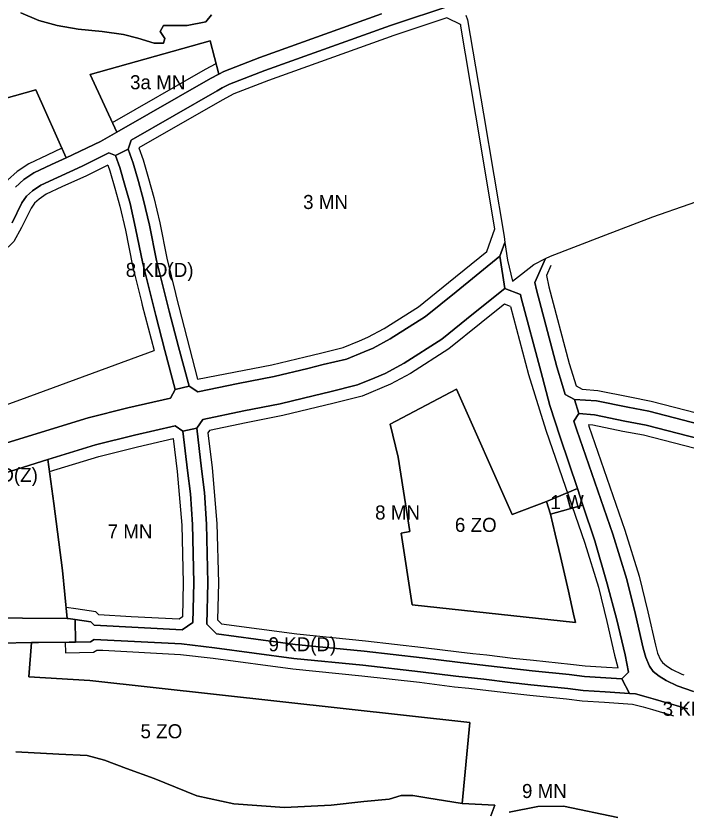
# Model space of a CAD drawing. Extents: x 7418056 to 7420315, y 5537846 to 5539505.
# Drawn here: x 7418849 to 7419326, y 5538474 to 5539041 of the extents above; entities that cross this region are included whole.
import ezdxf

# ---------------------------------------------------------------- set-up
doc = ezdxf.new("R2010")
doc.units = 0
for name, color, linetype in [('linie_rozgraniczajace', 7, 'Continuous'), ('linie_zabudowy_nieprzekraczalne', 7, 'Continuous'), ('oznaczenia_przeznaczen', 7, 'Continuous')]:
    doc.layers.add(name, color=color, linetype=linetype)

msp = doc.modelspace()

# ---------------------------------------------------------------- linework, layer by layer
at = {"layer": 'linie_rozgraniczajace'}
for points in [[(7419160.31, 5539049.03), (7419115.83, 5539034.15), (7419026.26, 5539002.12), (7419001.08, 5538992.37), (7418996.02, 5538989.83), (7418992.47, 5538987.64), (7418931.07, 5538952.54), (7418928.94, 5538946.14), (7418919.94, 5538941.63), (7418915.16, 5538943.43), (7418913.94, 5538942.73), (7418896.26, 5538934.01), (7418878.7, 5538926.05), (7418866.85, 5538920.51), (7418860.9, 5538916.51), (7418856.55, 5538912.53), (7418853.39, 5538907.77), (7418846.35, 5538893.73)], [(7419169.45, 5539041.55), (7419170.63, 5539038.31), (7419182.09, 5538971.36), (7419196.68, 5538883.86), (7419197.31, 5538879.71), (7419193.8, 5538869.94), (7419162.51, 5538844.52), (7419140.66, 5538826.97), (7419115.55, 5538810.89), (7419103.46, 5538804.38), (7419097.12, 5538801.74), (7419084.62, 5538796.58), (7419067.95, 5538792.6), (7419057.02, 5538789.95), (7419033.05, 5538784.14), (7419007.36, 5538779.18), (7418978.69, 5538773.11), (7418972.52, 5538777.28), (7418964.83, 5538805.21), (7418958.22, 5538830.78), (7418949.28, 5538866.87), (7418944.15, 5538892.03), (7418940.07, 5538909.81), (7418936.36, 5538923.15), (7418932.65, 5538936.07), (7418928.94, 5538946.14), (7418931.07, 5538952.54), (7418992.47, 5538987.64), (7418996.02, 5538989.83), (7419001.08, 5538992.37), (7419026.26, 5539002.12), (7419115.83, 5539034.15), (7419160.31, 5539049.03)], [(7418848.89, 5538919.08), (7418854.7, 5538924.41), (7418861.91, 5538929.24), (7418874.51, 5538935.14), (7418884.95, 5538939.87), (7418909.25, 5538951.55), (7418921.06, 5538958.34), (7418987.73, 5538996.53), (7418993.51, 5538999.62), (7418997.17, 5539001.58), (7419022.76, 5539011.49), (7419109.39, 5539042.47)], [(7418852.68, 5539043.27), (7418865.34, 5539037.9), (7418878.57, 5539034.27), (7418893.38, 5539031.69), (7418910.45, 5539029.88), (7418925.8, 5539027.87), (7418935.87, 5539025.18), (7418947.51, 5539021.65), (7418954.26, 5539021.67), (7418955.12, 5539024.96), (7418951.91, 5539030.07), (7418954.09, 5539034.36), (7418970.99, 5539034.34), (7418984.37, 5539036.89), (7418988.28, 5539041.83)], [(7418988.28, 5539041.83), (7418984.37, 5539036.89), (7418970.99, 5539034.34), (7418954.09, 5539034.36), (7418951.91, 5539030.07), (7418955.12, 5539024.96), (7418954.26, 5539021.67), (7418947.51, 5539021.65), (7418935.87, 5539025.18), (7418925.8, 5539027.87), (7418910.45, 5539029.88), (7418893.38, 5539031.69), (7418878.57, 5539034.27), (7418865.34, 5539037.9), (7418852.68, 5539043.27)], [(7419109.39, 5539042.47), (7419022.76, 5539011.49), (7418997.17, 5539001.58)], [(7418997.17, 5539001.58), (7418993.51, 5538999.62), (7418987.39, 5539023.42), (7418902.04, 5538999.34), (7418921.06, 5538958.34), (7418909.25, 5538951.55), (7418884.95, 5538939.87), (7418863.26, 5538988.38), (7418809.94, 5538973.34)], [(7418809.94, 5538973.34), (7418863.26, 5538988.38), (7418884.95, 5538939.87), (7418874.51, 5538935.14), (7418861.91, 5538929.24), (7418854.7, 5538924.41), (7418848.89, 5538919.08)], [(7418846.35, 5538893.73), (7418853.39, 5538907.77), (7418856.55, 5538912.53), (7418860.9, 5538916.51), (7418866.85, 5538920.51), (7418878.7, 5538926.05), (7418896.26, 5538934.01), (7418913.94, 5538942.73), (7418915.16, 5538943.43), (7418919.94, 5538941.63), (7418923.14, 5538932.95), (7418926.74, 5538920.43), (7418930.38, 5538907.35), (7418934.37, 5538889.91), (7418939.52, 5538864.68), (7418948.74, 5538827.5), (7418955.15, 5538802.69), (7418962.6, 5538774.99), (7418959.07, 5538768.78), (7418928.88, 5538761.73), (7418900.44, 5538754.64), (7418830.07, 5538733.01)], [(7419445.05, 5538721.75), (7419299.76, 5538759.34), (7419284.77, 5538762.18), (7419262.47, 5538766.8), (7419246.91, 5538767.82), (7419240.3, 5538771.3), (7419238.22, 5538777.64), (7419234.4, 5538791.06), (7419219.93, 5538845.79), (7419218.69, 5538851.22), (7419226.21, 5538868.16), (7419229.78, 5538869.96), (7419266.22, 5538883.99), (7419302.67, 5538898.01), (7419354.38, 5538915.86)], [(7419193.8, 5538869.94), (7419197.31, 5538879.71), (7419199.26, 5538867.11), (7419202.74, 5538852.14), (7419209.04, 5538857.05), (7419217.86, 5538863.95), (7419226.21, 5538868.16), (7419218.69, 5538851.22), (7419219.93, 5538845.79), (7419234.4, 5538791.06), (7419238.22, 5538777.64), (7419240.3, 5538771.3), (7419246.91, 5538767.82), (7419249.9, 5538757.72), (7419246.5, 5538752.37), (7419248.59, 5538745.99), (7419274.18, 5538671.86), (7419284.18, 5538639.55), (7419290.38, 5538614.44), (7419295.8, 5538590.55), (7419297.6, 5538583.9), (7419300.28, 5538577.86), (7419302.97, 5538574.06), (7419307.22, 5538570.67), (7419312.08, 5538567.46), (7419319.89, 5538563.81), (7419331.61, 5538559.58)], [(7418830.07, 5538733.01), (7418900.44, 5538754.64), (7418928.88, 5538761.73), (7418959.07, 5538768.78), (7418962.6, 5538774.99), (7418972.52, 5538777.28), (7418978.69, 5538773.11), (7419007.36, 5538779.18), (7419033.05, 5538784.14), (7419057.02, 5538789.95), (7419067.95, 5538792.6), (7419084.62, 5538796.58), (7419097.12, 5538801.74), (7419103.46, 5538804.38), (7419115.55, 5538810.89), (7419140.66, 5538826.97), (7419162.51, 5538844.52), (7419193.8, 5538869.94), (7419197.25, 5538846.73), (7419175.03, 5538828.93), (7419152.35, 5538810.7), (7419125.7, 5538793.64), (7419112.07, 5538786.3), (7419104.79, 5538783.26), (7419092.25, 5538778.09), (7419072.64, 5538773.16), (7419061.83, 5538770.53), (7419037.31, 5538764.59), (7419011.32, 5538759.57), (7418982.12, 5538753.4), (7418977.82, 5538747.4), (7418968.01, 5538745.28), (7418962.54, 5538749.08), (7418933.57, 5538742.29), (7418905.8, 5538735.36), (7418871.76, 5538724.9), (7418836.1, 5538713.94)], [(7419327.41, 5538547.33), (7419319.28, 5538549.7), (7419312.66, 5538551.61), (7419304.62, 5538553.96), (7419297.92, 5538555.91), (7419290.4, 5538558.1), (7419285.99, 5538558.34), (7419280.63, 5538568.76), (7419285.24, 5538573.49), (7419282.94, 5538585.76), (7419277.11, 5538610.78), (7419270.23, 5538636.52), (7419261.4, 5538667.14), (7419252.88, 5538692.56), (7419248.94, 5538704.31), (7419236.65, 5538740.96), (7419229.28, 5538763.46), (7419222.83, 5538787.88), (7419209, 5538840.19), (7419208.37, 5538842.57), (7419197.25, 5538846.73), (7419193.8, 5538869.94)], [(7419442.55, 5538712.07), (7419297.9, 5538749.52), (7419282.83, 5538752.37), (7419261.07, 5538756.88), (7419249.9, 5538757.72), (7419246.91, 5538767.82), (7419262.47, 5538766.8), (7419284.77, 5538762.18), (7419299.76, 5538759.34), (7419445.05, 5538721.75)], [(7419331.61, 5538559.58), (7419319.89, 5538563.81), (7419312.08, 5538567.46), (7419307.22, 5538570.67), (7419302.97, 5538574.06), (7419300.28, 5538577.86), (7419297.6, 5538583.9), (7419295.8, 5538590.55), (7419290.38, 5538614.44), (7419284.18, 5538639.55), (7419274.18, 5538671.86), (7419248.59, 5538745.99), (7419246.5, 5538752.37), (7419249.9, 5538757.72), (7419261.07, 5538756.88), (7419282.83, 5538752.37), (7419297.9, 5538749.52), (7419442.55, 5538712.07)], [(7418836.1, 5538713.94), (7418871.76, 5538724.9), (7418876.01, 5538693.69), (7418882.21, 5538645.85), (7418885.71, 5538611.77), (7418853.86, 5538611.94), (7418837.03, 5538612.11)], [(7418837.03, 5538612.11), (7418853.86, 5538611.94), (7418885.71, 5538611.77), (7418886.34, 5538611.65), (7418891.32, 5538611.05), (7418891.64, 5538594.92), (7418887.02, 5538594.78), (7418865.29, 5538594.71), (7418860.23, 5538594.58), (7418838.16, 5538594.04)], [(7418838.16, 5538594.04), (7418860.23, 5538594.58), (7418858.38, 5538570.15), (7418901.82, 5538567.44), (7419172.23, 5538537.66), (7419166.81, 5538479.9), (7419141.82, 5538484.04), (7419131.75, 5538485.55), (7419123.56, 5538485.53), (7419114.83, 5538482.98), (7419096.93, 5538481.3), (7419073.69, 5538478.78), (7419040.33, 5538477.11), (7419004.29, 5538479.75), (7418977.88, 5538485.29), (7418947.59, 5538497.69), (7418927.76, 5538504.76), (7418912.06, 5538510.74), (7418899.95, 5538514.03), (7418879.72, 5538515.1), (7418849.07, 5538516.69)], [(7419187.23, 5538471.09), (7419190.15, 5538478.7), (7419166.81, 5538479.9), (7419172.23, 5538537.66), (7418901.82, 5538567.44), (7418858.38, 5538570.15), (7418860.23, 5538594.58), (7418865.29, 5538594.71), (7418887.02, 5538594.78), (7418891.64, 5538594.92), (7418902.09, 5538595.12), (7418904.86, 5538596.86), (7418966.99, 5538593.54), (7418990.58, 5538590.89), (7419047.02, 5538583.32), (7419096.11, 5538578.4), (7419137.33, 5538573.76), (7419162.43, 5538570.57), (7419182.35, 5538568.37), (7419201.04, 5538566.12), (7419215.74, 5538564.54), (7419242.02, 5538561.82), (7419252.98, 5538560.44), (7419268.68, 5538559.53), (7419285.99, 5538558.34), (7419290.4, 5538558.1), (7419297.92, 5538555.91), (7419304.62, 5538553.96), (7419312.66, 5538551.61), (7419319.28, 5538549.7), (7419327.41, 5538547.33)], [(7418849.07, 5538516.69), (7418879.72, 5538515.1), (7418899.95, 5538514.03), (7418912.06, 5538510.74), (7418927.76, 5538504.76), (7418947.59, 5538497.69), (7418977.88, 5538485.29), (7419004.29, 5538479.75), (7419040.33, 5538477.11), (7419073.69, 5538478.78), (7419096.93, 5538481.3), (7419114.83, 5538482.98), (7419123.56, 5538485.53), (7419131.75, 5538485.55), (7419141.82, 5538484.04), (7419166.81, 5538479.9), (7419190.15, 5538478.7), (7419187.23, 5538471.09)], [(7419277.73, 5538469.82), (7419238.97, 5538477.94), (7419220.85, 5538477.69), (7419200.36, 5538473.67)], [(7419200.36, 5538473.67), (7419220.85, 5538477.69), (7419238.97, 5538477.94), (7419277.73, 5538469.82)]]:
    msp.add_lwpolyline(points, dxfattribs=at)
for points in [[(7418902.04, 5538999.34), (7418987.39, 5539023.42), (7418993.51, 5538999.62), (7418987.73, 5538996.53), (7418921.06, 5538958.34)], [(7418919.94, 5538941.63), (7418928.94, 5538946.14), (7418932.65, 5538936.07), (7418936.36, 5538923.15), (7418940.07, 5538909.81), (7418944.15, 5538892.03), (7418949.28, 5538866.87), (7418958.22, 5538830.78), (7418964.83, 5538805.21), (7418972.52, 5538777.28), (7418962.6, 5538774.99), (7418955.15, 5538802.69), (7418948.74, 5538827.5), (7418939.52, 5538864.68), (7418934.37, 5538889.91), (7418930.38, 5538907.35), (7418926.74, 5538920.43), (7418923.14, 5538932.95)], [(7418977.82, 5538747.4), (7418982.12, 5538753.4), (7419011.32, 5538759.57), (7419037.31, 5538764.59), (7419061.83, 5538770.53), (7419072.64, 5538773.16), (7419092.25, 5538778.09), (7419104.79, 5538783.26), (7419112.07, 5538786.3), (7419125.7, 5538793.64), (7419152.35, 5538810.7), (7419175.03, 5538828.93), (7419197.25, 5538846.73), (7419208.37, 5538842.57), (7419209, 5538840.19), (7419222.83, 5538787.88), (7419229.28, 5538763.46), (7419236.65, 5538740.96), (7419248.94, 5538704.31), (7419226.86, 5538694.97), (7419202.55, 5538685.76), (7419162.85, 5538775.08), (7419115.51, 5538750.08), (7419121.22, 5538726.71), (7419129.55, 5538673.65), (7419123.39, 5538672.41), (7419131.25, 5538621.36), (7419247.63, 5538608.96), (7419246.27, 5538614.84), (7419242.51, 5538631.17), (7419236.8, 5538655.87), (7419233.15, 5538671.75), (7419229.7, 5538685.93), (7419252.88, 5538692.56), (7419261.4, 5538667.14), (7419270.23, 5538636.52), (7419277.11, 5538610.78), (7419282.94, 5538585.76), (7419285.24, 5538573.49), (7419280.63, 5538568.76), (7419269.29, 5538569.51), (7419253.9, 5538570.41), (7419243.15, 5538571.75), (7419216.79, 5538574.48), (7419202.18, 5538576.05), (7419183.5, 5538578.31), (7419163.61, 5538580.5), (7419138.52, 5538583.69), (7419097.17, 5538588.34), (7419048.02, 5538593.27), (7418991.91, 5538600.79), (7418984.98, 5538607.62), (7418985.77, 5538637.14), (7418984.74, 5538679.01), (7418983.39, 5538701.43), (7418981.32, 5538718.3)], [(7419115.51, 5538750.08), (7419162.85, 5538775.08), (7419202.55, 5538685.76), (7419226.86, 5538694.97), (7419229.7, 5538685.93), (7419233.15, 5538671.75), (7419236.8, 5538655.87), (7419242.51, 5538631.17), (7419246.27, 5538614.84), (7419247.63, 5538608.96), (7419131.25, 5538621.36), (7419123.39, 5538672.41), (7419129.55, 5538673.65), (7419121.22, 5538726.71)], [(7418871.76, 5538724.9), (7418905.8, 5538735.36), (7418933.57, 5538742.29), (7418962.54, 5538749.08), (7418968.01, 5538745.28), (7418971.4, 5538717.1), (7418973.42, 5538700.53), (7418974.75, 5538678.59), (7418975.77, 5538637.14), (7418975.02, 5538608.95), (7418967.53, 5538603.53), (7418904.75, 5538606.91), (7418902.39, 5538609.43), (7418891.32, 5538611.05), (7418886.34, 5538611.65), (7418885.71, 5538611.77), (7418882.21, 5538645.85), (7418876.01, 5538693.69)], [(7418891.64, 5538594.92), (7418891.32, 5538611.05), (7418902.39, 5538609.43), (7418904.75, 5538606.91), (7418967.53, 5538603.53), (7418975.02, 5538608.95), (7418975.77, 5538637.14), (7418974.75, 5538678.59), (7418973.42, 5538700.53), (7418971.4, 5538717.1), (7418968.01, 5538745.28), (7418977.82, 5538747.4), (7418981.32, 5538718.3), (7418983.39, 5538701.43), (7418984.74, 5538679.01), (7418985.77, 5538637.14), (7418984.98, 5538607.62), (7418991.91, 5538600.79), (7419048.02, 5538593.27), (7419097.17, 5538588.34), (7419138.52, 5538583.69), (7419163.61, 5538580.5), (7419183.5, 5538578.31), (7419202.18, 5538576.05), (7419216.79, 5538574.48), (7419243.15, 5538571.75), (7419253.9, 5538570.41), (7419269.29, 5538569.51), (7419280.63, 5538568.76), (7419285.99, 5538558.34), (7419268.68, 5538559.53), (7419252.98, 5538560.44), (7419242.02, 5538561.82), (7419215.74, 5538564.54), (7419201.04, 5538566.12), (7419182.35, 5538568.37), (7419162.43, 5538570.57), (7419137.33, 5538573.76), (7419096.11, 5538578.4), (7419047.02, 5538583.32), (7418990.58, 5538590.89), (7418966.99, 5538593.54), (7418904.86, 5538596.86), (7418902.09, 5538595.12)], [(7419226.86, 5538694.97), (7419248.94, 5538704.31), (7419252.88, 5538692.56), (7419229.7, 5538685.93)]]:
    msp.add_lwpolyline(points, close=True, dxfattribs=at)
at = {"layer": 'linie_zabudowy_nieprzekraczalne'}
for points in [[(7419166.2, 5539034.79), (7419156.01, 5539039.69), (7419118.28, 5539027.06), (7419028.87, 5538995.09), (7419004.34, 5538985.59), (7418996.09, 5538981.07), (7418936.59, 5538947.05), (7418939.78, 5538938.41), (7418943.58, 5538925.19), (7418947.34, 5538911.65), (7418951.47, 5538893.63), (7418956.61, 5538868.52), (7418962.76, 5538843.31), (7418963.29, 5538841.12), (7418978.5, 5538782.26)], [(7418978.5, 5538782.26), (7419031.25, 5538792.45), (7419055.02, 5538798.21), (7419065.96, 5538800.86), (7419082.09, 5538804.74), (7419093.86, 5538809.59), (7419099.79, 5538812.07), (7419111.24, 5538818.23), (7419135.69, 5538833.88), (7419157.17, 5538851.14), (7419184.35, 5538873.22), (7419190.18, 5538889.42), (7419176.67, 5538970.46), (7419165.61, 5539035.08)], [(7418917.9, 5538965.17), (7418984, 5539003.04), (7418991.59, 5539007.1)], [(7418881.89, 5538946.72), (7418871.38, 5538941.95), (7418858.22, 5538935.79), (7418850.06, 5538930.32), (7418843.14, 5538924), (7418838.22, 5538916.56), (7418830.85, 5538901.86), (7418827.48, 5538895.72), (7418823.82, 5538892.18), (7418819.12, 5538889.07), (7418811.92, 5538886.15), (7418750.1, 5538860.3), (7418720.17, 5538848.81), (7418711.52, 5538845.75), (7418705.48, 5538843.88), (7418690.55, 5538841.44), (7418683.51, 5538840.72)], [(7418914.52, 5538934.66), (7418899.46, 5538927.23), (7418881.84, 5538919.25), (7418870.55, 5538913.97), (7418865.54, 5538910.61), (7418862.29, 5538907.63), (7418859.89, 5538904.01), (7418852.99, 5538890.25), (7418847.58, 5538880.37), (7418839.53, 5538872.6), (7418830.83, 5538866.85), (7418821.44, 5538863.04), (7418759.41, 5538837.1), (7418728.82, 5538825.35), (7418719.39, 5538822.02), (7418711.22, 5538819.48), (7418696.52, 5538817.09)], [(7418914.52, 5538934.66), (7418916.01, 5538930.62), (7418919.52, 5538918.4), (7418923.1, 5538905.51), (7418927.04, 5538888.33), (7418932.21, 5538863.05), (7418938.47, 5538837.38), (7418939.05, 5538835.03), (7418947.43, 5538802.58)], [(7419230.05, 5538863.26), (7419226.83, 5538855.99), (7419228.66, 5538847.95), (7419243.08, 5538793.44), (7419247.97, 5538777.43), (7419252.45, 5538775.08), (7419263.51, 5538774.25), (7419286.23, 5538769.54), (7419301.46, 5538766.66), (7419390.96, 5538743.5)], [(7419197.02, 5538835.72), (7419192.58, 5538832.1), (7419180.34, 5538822.3), (7419157.32, 5538803.8), (7419130.01, 5538786.31), (7419115.75, 5538778.64), (7419095.68, 5538770.2), (7419074.68, 5538764.91), (7419063.83, 5538762.28), (7419039.12, 5538756.29), (7419013.01, 5538751.24), (7418987.02, 5538745.75), (7418985.78, 5538744.08), (7418988.79, 5538719), (7418992.23, 5538679.5), (7418993.27, 5538637.13), (7418992.57, 5538610.69), (7418995.39, 5538607.9), (7419049.14, 5538600.69), (7419097.97, 5538595.8), (7419139.41, 5538591.14), (7419164.49, 5538587.96), (7419174.5, 5538586.85), (7419184.37, 5538585.76), (7419203.02, 5538583.51), (7419217.57, 5538581.95), (7419244.01, 5538579.21), (7419254.58, 5538577.88), (7419269.76, 5538577), (7419277.94, 5538576.46)], [(7419201.29, 5538834.12), (7419197.02, 5538835.72)], [(7419201.29, 5538834.12), (7419214.15, 5538785.5), (7419226.54, 5538745.83), (7419254.21, 5538665.33), (7419263.93, 5538633.92), (7419269.94, 5538609.6), (7419275.42, 5538585.48), (7419277.75, 5538576.87), (7419277.94, 5538576.46)], [(7418707.95, 5538722.19), (7418777.45, 5538740.64), (7418852.61, 5538767.82), (7418947.43, 5538802.58)], [(7419368.6, 5538723.46), (7419296, 5538742.25), (7419281.37, 5538745.02), (7419260.02, 5538749.44), (7419256.85, 5538749.68), (7419257.12, 5538748.86), (7419282.73, 5538674.66), (7419292.85, 5538641.96), (7419299.13, 5538616.52), (7419304.54, 5538592.72), (7419306.11, 5538586.92), (7419308.15, 5538582.33), (7419309.58, 5538580.3), (7419312.51, 5538577.96), (7419316.49, 5538575.34), (7419323.33, 5538572.13), (7419324.73, 5538571.63)], [(7418872.93, 5538716.37), (7418908.08, 5538727.18), (7418935.57, 5538734.04), (7418961.09, 5538740.01), (7418963.93, 5538716.42), (7418967.26, 5538678.11), (7418968.27, 5538637.16), (7418967.62, 5538612.86), (7418965.28, 5538611.17), (7418931.14, 5538613.01), (7418908.15, 5538614.24), (7418906.01, 5538616.48), (7418891.76, 5538618.56), (7418884.92, 5538619.49)], [(7418884.22, 5538594.78), (7418884.41, 5538587.3)], [(7418884.42, 5538587.3), (7418904.28, 5538587.65), (7418906.83, 5538589.25), (7418911.04, 5538589.05), (7418966.38, 5538586.07), (7418989.61, 5538583.45), (7419046.23, 5538575.86), (7419095.32, 5538570.94), (7419136.44, 5538566.31), (7419161.54, 5538563.13), (7419171.75, 5538562), (7419181.5, 5538560.92), (7419200.19, 5538558.67), (7419214.96, 5538557.09), (7419241.16, 5538554.37), (7419252.29, 5538552.97), (7419268.22, 5538552.04), (7419288.3, 5538550.72), (7419295.83, 5538548.71), (7419302.53, 5538546.76), (7419316.64, 5538542.66), (7419317.45, 5538542.37)], [(7419281.92, 5538567.47), (7419281.92, 5538567.47), (7419281.92, 5538567.47)]]:
    msp.add_lwpolyline(points, dxfattribs=at)

# ---------------------------------------------------------------- texts
at = {"layer": 'oznaczenia_przeznaczen'}
for s, p in [('3a MN', (7418930.38, 5538988.82)), ('3 MN', (7419053.61, 5538903.48)), ('8 KD(D)', (7418927.3, 5538855.09)), ('1 KD(Z)', (7418817.93, 5538709.01)), ('1 W', (7419229.67, 5538689.65)), ('8 MN', (7419104.89, 5538682.24)), ('6 ZO', (7419161.72, 5538673.4)), ('7 MN', (7418914.41, 5538668.74)), ('9 KD(D)', (7419028.99, 5538588.35)), ('3 KD(L)', (7419309.69, 5538542.4)), ('5 ZO', (7418937.82, 5538526.36)), ('9 MN', (7419209.48, 5538483.79))]:
    msp.add_text(s, height=10, dxfattribs=at).set_placement(p)

doc.saveas('drawing.dxf')
